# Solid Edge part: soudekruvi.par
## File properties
Author: Blackblade
Template: Normal.par
Last saved by: Blackblade
Revision: 16
Application: Solid Edge
Accuracy: 0.99
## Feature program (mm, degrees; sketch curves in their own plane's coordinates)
sketch for "unnamed Protrusion 1" plane through (0, 0, 0) normal (0, -1, 0) x-axis (1, 0, 0)
  circle centre (0, 0) radius 2.5
extrude "unnamed Protrusion 1" add
lofted protrusion "unnamed LoftedProtrusion 1"
pattern "unnamed Pattern 1" of "unnamed LoftedProtrusion 1"
lofted protrusion "unnamed LoftedProtrusion 2"
lofted protrusion "unnamed LoftedProtrusion 3"
lofted protrusion "unnamed LoftedProtrusion 4"
lofted protrusion "unnamed LoftedProtrusion 5"
fillet "Round_1" radius 0.5
sketch for "ExtrudedCutout_1" plane through (0, 0, 0) normal (0, 1, 0) x-axis (0, 0, -1)
  circle centre (0, 0) radius 2.5
extrude "ExtrudedCutout_1" cut
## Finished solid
Body 1: solid body, 19 faces, 37 edges, 25 vertices.
  Faces by surface: plane 7, blend 5, spline 5, cylinder 2
  Edges by curve: intersection 35, circle 2
Bounding box of the edges (mm; curved faces can reach further): 20.993 x 9.549 x 21.324, from (-10.6096, -14, -10.2877) to (10.3831, -4.4512, 11.0366).
Cylindrical faces by radius (mm): R2.5 x2
Planar faces by outward normal: +y 1, -y 1, oblique 5
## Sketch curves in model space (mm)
arc centre (1.9134, -10, 4.6194) radius 2 from (3.6842, -10.5714, 3.8859) through (1.0095, -11.7443, 4.9938) to (0.5398, -8.6623, 5.1884)
arc centre (39.099, -21.9996, -10.7834) radius 40 from (5.0737, -6.3902, 3.3103) through (4.3253, -8.4599, 3.6204) to (3.6842, -10.5714, 3.8859)
arc centre (4.2231, -6, 3.6627) radius 1 from (3.5871, -5.2747, 3.9261) through (4.7936, -5.2134, 3.4264) to (5.0737, -6.3902, 3.3103)
arc centre (41.7491, -48.7924, -11.8811) radius 60 from (0.5398, -8.6623, 5.1884) through (2.0326, -6.936, 4.57) to (3.5871, -5.2747, 3.9261)
arc centre (7.0711, -10, 7.0711) radius 3 from (8.5953, -12.0864, 5.5468) through (5.4009, -11.8496, 8.7412) to (5.8963, -7.502, 8.2458)
arc centre (28.9191, -39.9053, -14.7769) radius 40 from (11.0183, -8.9356, 3.1238) through (9.7744, -10.4611, 4.3678) to (8.5953, -12.0864, 5.5468)
arc centre (9.8995, -7, 4.2426) radius 2.5 from (9.052, -4.806, 5.0901) through (11.3944, -5.6656, 2.7478) to (11.0183, -8.9356, 3.1238)
arc centre (29.391, -57.462, -15.2489) radius 60 from (5.8963, -7.502, 8.2458) through (7.4535, -6.1055, 6.6887) to (9.052, -4.806, 5.0901)
arc centre (0, -10, 0) radius 1 from (0.3501, -10.9367, 0) through (-0.9759, -10.2182, 0) to (-0.1416, -9.0101, 0)
arc centre (14.3559, -48.4045, 0) radius 40 from (5.1155, -9.4865, 0) through (2.7102, -10.1373, 0) to (0.3501, -10.9367, 0)
arc centre (5, -9, 0) radius 0.5 from (4.9718, -8.5008, 0) through (5.4967, -8.9426, 0) to (5.1155, -9.4865, 0)
arc centre (8.3561, -68.4053, 0) radius 60 from (-0.1416, -9.0101, 0) through (2.4096, -8.7007, 0) to (4.9718, -8.5008, 0)
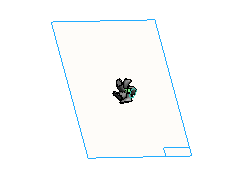
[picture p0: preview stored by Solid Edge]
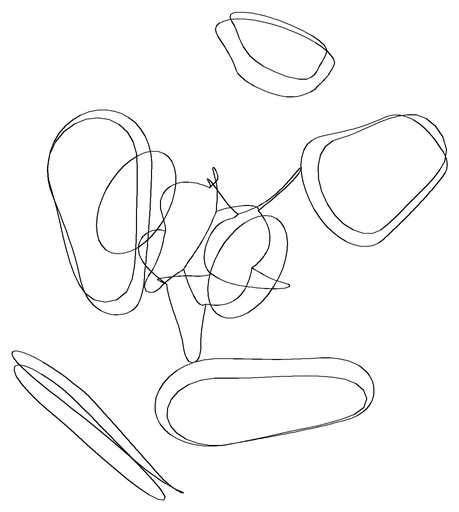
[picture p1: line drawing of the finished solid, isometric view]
